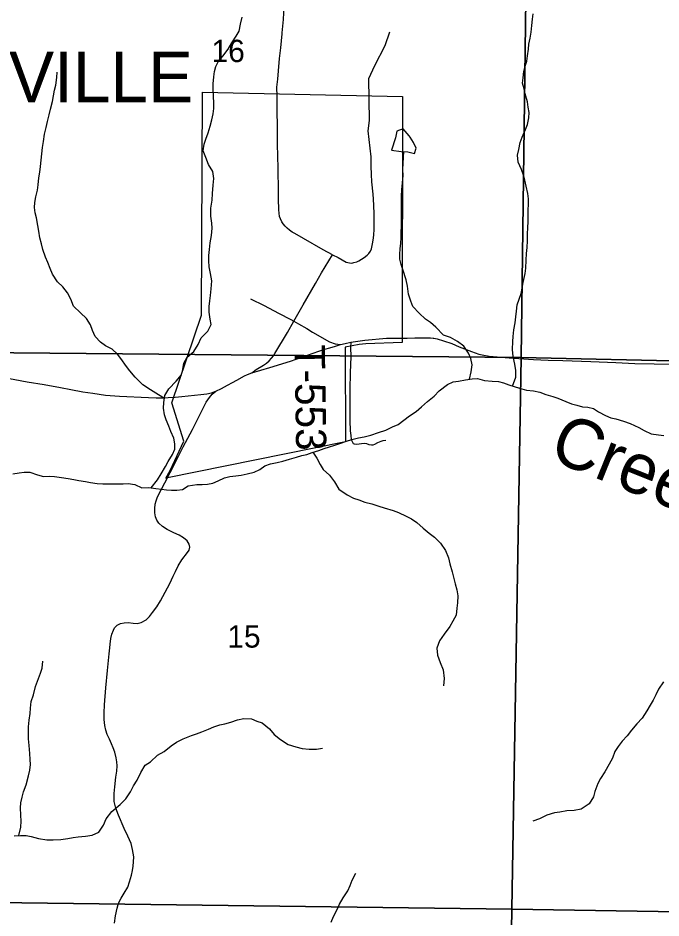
# Model space of a CAD drawing. Extents: x 0 to 191, y 0 to 55.
# Drawn here: x 187.422 to 188.627, y 50.382 to 52.068 of the extents above; entities that cross this region are included whole.
import ezdxf

# ---------------------------------------------------------------- set-up
doc = ezdxf.new("R2010")
doc.units = 0
for name, color, linetype in [('GM_X_City_Street', 7, 'Continuous'), ('GM_X_Corporation', 7, 'Continuous'), ('GM_X_Corporation_Text', 7, 'Continuous'), ('GM_X_Minor_Lake', 7, 'Continuous'), ('GM_X_Minor_River', 7, 'Continuous'), ('GM_X_Minor_River_Text', 7, 'Continuous'), ('GM_X_Section_Text', 7, 'Continuous'), ('GM_X_State_Route', 7, 'Continuous'), ('GM_X_Township_Road', 7, 'Continuous'), ('GM_X_Township_Road_Text', 7, 'Continuous')]:
    doc.layers.add(name, color=color, linetype=linetype)

msp = doc.modelspace()

# ---------------------------------------------------------------- linework, layer by layer
at = {"layer": 'GM_X_City_Street'}
for points in [[(187.8578, 51.5417), (187.8832, 51.5291), (187.9106, 51.5152), (187.9332, 51.5032), (187.9392, 51.4997), (187.9478, 51.4948)], [(187.9478, 51.4948), (187.9633, 51.486), (187.9742, 51.4791), (188.0061, 51.461), (188.0168, 51.4577), (188.0267, 51.4565)]]:
    msp.add_lwpolyline(points, dxfattribs=at)
at = {"layer": 'GM_X_Corporation'}
for points in [[(187.3608, 52.4557), (188.3785, 52.4395), (188.3652, 51.4321), (187.3457, 51.441)], [(188.3785, 52.4395), (189.3902, 52.4217), (189.3789, 51.4094), (188.3652, 51.4321)], [(187.6988, 51.2057), (187.7072, 51.2202), (187.7328, 51.2751), (187.7105, 51.3468), (187.7659, 51.5111), (187.7676, 51.929), (188.1426, 51.9211), (188.1418, 51.4599), (188.074, 51.4574), (188.0613, 51.4561), (188.0352, 51.4511), (188.036, 51.2741)], [(188.3652, 51.4321), (188.3474, 50.3984), (187.3319, 50.4112), (187.3457, 51.441)], [(189.3789, 51.4094), (189.3658, 50.3822), (188.3474, 50.3984), (188.3652, 51.4321)], [(187.3319, 50.4112), (188.3474, 50.3984), (188.3312, 49.3807), (187.315, 49.3912)], [(188.3474, 50.3984), (189.3658, 50.3822), (189.3602, 49.3699), (188.3312, 49.3807)]]:
    msp.add_lwpolyline(points, close=True, dxfattribs=at)
at = {"layer": 'GM_X_Minor_Lake'}
for points in [[(188.1568, 51.8446), (188.1552, 51.8471), (188.1438, 51.86), (188.1324, 51.8557), (188.1298, 51.8436), (188.122, 51.8205)], [(188.122, 51.8205), (188.1404, 51.8178), (188.153, 51.8171), (188.1655, 51.8141), (188.1681, 51.8243), (188.1632, 51.8346), (188.1568, 51.8446)]]:
    msp.add_lwpolyline(points, dxfattribs=at)
at = {"layer": 'GM_X_Minor_River'}
for points in [[(187.6719, 51.1877), (187.6834, 51.2024), (187.6902, 51.2142), (187.6982, 51.2275), (187.7035, 51.2371), (187.7118, 51.25), (187.7159, 51.2603), (187.7159, 51.2701), (187.714, 51.2804), (187.7083, 51.2929), (187.7045, 51.3031), (187.6999, 51.3149), (187.6968, 51.3247), (187.6949, 51.3369), (187.6953, 51.3475), (187.6971, 51.3608), (187.7047, 51.373), (187.7187, 51.3874), (187.7282, 51.3992), (187.7308, 51.4091), (187.733, 51.4213), (187.7391, 51.4327), (187.7516, 51.4433), (187.7599, 51.4559), (187.7656, 51.4688), (187.7781, 51.481), (187.7841, 51.4936), (187.7822, 51.5034), (187.7806, 51.5167), (187.7806, 51.5273), (187.7813, 51.538), (187.7828, 51.5479), (187.7839, 51.5604), (187.7851, 51.5752), (187.7827, 51.5892), (187.7801, 51.6014), (187.7797, 51.6131), (187.78, 51.623), (187.7807, 51.634), (187.7822, 51.6466), (187.7849, 51.6606), (187.786, 51.6743), (187.7852, 51.6838), (187.7836, 51.6967), (187.7836, 51.7119), (187.7858, 51.7263), (187.7866, 51.7388), (187.7881, 51.7544), (187.7892, 51.7673), (187.7869, 51.7802), (187.7792, 51.7935), (187.7743, 51.8064), (187.7689, 51.8193), (187.7708, 51.8314), (187.7742, 51.8409), (187.7787, 51.8527), (187.7825, 51.8653), (187.7855, 51.877), (187.7877, 51.8881), (187.7889, 51.8983), (187.7888, 51.909), (187.7884, 51.9211), (187.7876, 51.934), (187.7876, 51.9443), (187.7891, 51.9579), (187.7902, 51.9674), (187.7928, 51.9769), (187.7981, 51.9868), (187.8057, 51.9963), (187.8159, 52.0093), (187.8227, 52.0211), (187.831, 52.0336), (187.8363, 52.0432), (187.8393, 52.0561), (187.8423, 52.0694)], [(188.3489, 51.3783), (188.3554, 51.3948), (188.355, 51.4077), (188.3531, 51.4191), (188.35, 51.4335), (188.3489, 51.4471), (188.3496, 51.4616), (188.3503, 51.4711), (188.3514, 51.4836), (188.3537, 51.4965), (188.3552, 51.5079), (188.3563, 51.5189), (188.3578, 51.5303), (188.3615, 51.5409), (188.3649, 51.5516), (188.3672, 51.5615), (188.3691, 51.5725), (188.3728, 51.5892), (188.3739, 51.5995), (188.3747, 51.6139), (188.3754, 51.6268), (188.3765, 51.6378), (188.3769, 51.6507), (188.3772, 51.6629), (188.3776, 51.6754), (188.3783, 51.686), (188.3782, 51.7088), (188.3786, 51.7187), (188.3786, 51.7293), (188.3778, 51.7388), (188.3747, 51.7528), (188.3717, 51.7642), (188.3694, 51.7737), (188.3659, 51.7843), (188.3598, 51.798), (188.3583, 51.8109), (188.3605, 51.8215), (188.3635, 51.8348), (188.3673, 51.8447), (188.3733, 51.8588), (188.3767, 51.8683), (188.3797, 51.8808), (188.3801, 51.8907), (188.3785, 51.9009), (188.377, 51.9108), (188.3728, 51.9256), (188.3705, 51.9351), (188.3678, 51.9457), (188.3686, 51.9556), (188.3704, 51.9677), (188.3727, 51.9776), (188.3757, 51.9871), (188.3772, 51.997), (188.3791, 52.0095), (188.3798, 52.019), (188.382, 52.0301), (188.3839, 52.0415), (188.3854, 52.0536), (188.3865, 52.0654), (188.3876, 52.0756)], [(187.6963, 51.3552), (187.6854, 51.3619), (187.6705, 51.3713), (187.6561, 51.3808), (187.6416, 51.3948), (187.6314, 51.4069), (187.6234, 51.4175), (187.6165, 51.4274), (187.6085, 51.4383), (187.5983, 51.4474), (187.5861, 51.4538), (187.5766, 51.4606), (187.5667, 51.4712), (187.5614, 51.4826), (187.5579, 51.4932), (187.5507, 51.505), (187.5393, 51.5156), (187.526, 51.5277), (187.521, 51.5413), (187.5145, 51.5531), (187.5062, 51.5644), (187.4963, 51.5739), (187.4864, 51.5879), (187.4822, 51.5985), (187.478, 51.6099), (187.4734, 51.6201), (187.4684, 51.6342), (187.4658, 51.6448), (187.4631, 51.6562), (187.4611, 51.6683), (187.4592, 51.6793), (187.4565, 51.6934), (187.4542, 51.7029), (187.4531, 51.7127), (187.4534, 51.7222), (187.4557, 51.7329), (187.4583, 51.7454), (187.4598, 51.7556), (187.4613, 51.7686), (187.4632, 51.7792), (187.4639, 51.7895), (187.4654, 51.8016), (187.468, 51.8255), (187.4695, 51.8366), (187.4717, 51.8502), (187.4747, 51.8628), (187.4774, 51.8738), (187.4804, 51.8863), (187.483, 51.8974), (187.4864, 51.9114), (187.4886, 51.9221), (187.4905, 51.9327), (187.4931, 51.9422), (187.495, 51.9566), (187.4954, 51.9661)], [(188.2684, 51.3911), (188.2712, 51.4048), (188.273, 51.4184), (188.2707, 51.4302), (188.2665, 51.44), (188.2574, 51.4533), (188.2456, 51.462), (188.2327, 51.4692), (188.2198, 51.4737), (188.2053, 51.4888), (188.1954, 51.4971), (188.1859, 51.5036), (188.1738, 51.5149), (188.162, 51.5274), (188.1582, 51.5373), (188.154, 51.5502), (188.152, 51.5653), (188.1493, 51.5771), (188.1432, 51.5968), (188.1402, 51.6063), (188.1375, 51.6158), (188.1375, 51.6257), (188.1386, 51.6352), (188.1393, 51.6458), (188.1401, 51.656), (188.1404, 51.6663), (188.1408, 51.6788), (188.1407, 51.6887), (188.1411, 51.7012), (188.141, 51.7335), (188.1417, 51.7464), (188.1429, 51.7593), (188.144, 51.773), (188.1436, 51.784), (188.1453, 51.8175)], [(188.1685, 51.3308), (188.1783, 51.3392), (188.1897, 51.3491), (188.2018, 51.3597), (188.2117, 51.3696), (188.2268, 51.3811), (188.2378, 51.386), (188.2477, 51.3876), (188.2606, 51.3899), (188.2731, 51.3919), (188.2833, 51.3923), (188.2966, 51.3889), (188.3107, 51.3878), (188.3228, 51.3867), (188.3323, 51.3841), (188.3418, 51.3807), (188.352, 51.3773), (188.3619, 51.3743), (188.3752, 51.3705), (188.3885, 51.3691), (188.3999, 51.3668), (188.4113, 51.3627), (188.4242, 51.3589), (188.4341, 51.3555), (188.4489, 51.3495), (188.4595, 51.345), (188.4694, 51.3424), (188.4804, 51.3397), (188.4899, 51.3386), (188.5005, 51.336), (188.51, 51.3303), (188.5233, 51.3232), (188.5332, 51.319), (188.5427, 51.3168), (188.5571, 51.3123), (188.5693, 51.3081), (188.5856, 51.301), (188.5955, 51.2949), (188.6088, 51.2889), (188.6224, 51.2867), (188.6323, 51.2856)], [(187.4121, 51.2141), (187.4242, 51.216), (187.4337, 51.2172), (187.4443, 51.2172), (187.4588, 51.212), (187.4698, 51.209), (187.4804, 51.2098), (187.4903, 51.209), (187.5036, 51.2072), (187.5161, 51.2049), (187.5267, 51.2031), (187.5362, 51.2016), (187.5487, 51.1994), (187.5582, 51.1979), (187.5704, 51.196), (187.581, 51.1953), (187.5909, 51.1949), (187.606, 51.195), (187.619, 51.195), (187.6284, 51.1958), (187.6413, 51.1936), (187.6539, 51.1879), (187.6672, 51.1883), (187.6804, 51.1865), (187.6907, 51.1854), (187.7002, 51.1839), (187.7097, 51.1832), (187.7195, 51.1832), (187.7302, 51.1848), (187.7411, 51.1916), (187.7571, 51.1939), (187.7669, 51.194), (187.7772, 51.1948), (187.7871, 51.1967), (187.7973, 51.2005), (187.809, 51.2063), (187.8189, 51.2086), (187.8303, 51.2101), (187.8401, 51.2117), (187.8515, 51.2136), (187.8644, 51.2171), (187.875, 51.2217), (187.8849, 51.2289), (187.8955, 51.2327), (187.908, 51.2354), (187.9183, 51.2377), (187.9311, 51.2412), (187.944, 51.245), (187.9539, 51.2481), (187.9634, 51.2504), (187.9736, 51.2539), (187.9858, 51.2577), (187.9956, 51.2611), (188.0059, 51.2642), (188.0157, 51.2677), (188.0252, 51.2707), (188.0377, 51.2753), (188.0476, 51.2784), (188.0601, 51.2811), (188.0711, 51.2834), (188.0836, 51.2865), (188.098, 51.2911), (188.1113, 51.2957), (188.1238, 51.3018), (188.1344, 51.3064), (188.1454, 51.3144), (188.156, 51.3224), (188.1685, 51.3308)], [(187.9747, 51.2542), (187.982, 51.2433), (187.9881, 51.2315), (187.9938, 51.2217), (188.0056, 51.2114), (188.0151, 51.1986), (188.0235, 51.1849), (188.0387, 51.1743), (188.0508, 51.1683), (188.0607, 51.1649), (188.0721, 51.1608), (188.0854, 51.1574), (188.0983, 51.1533), (188.1086, 51.1503), (188.1253, 51.1454), (188.1351, 51.1412), (188.1496, 51.1348), (188.1598, 51.1296), (188.1697, 51.1224), (188.1815, 51.1118), (188.1929, 51.1027), (188.2024, 51.0955), (188.2138, 51.0838), (188.2233, 51.0702), (188.2291, 51.0565), (188.2314, 51.0451), (188.236, 51.03), (188.2386, 51.0205), (188.2417, 51.0076), (188.2444, 50.9966), (188.2463, 50.9852), (188.2459, 50.9719), (188.2448, 50.962), (188.2433, 50.9491), (188.2373, 50.9381), (188.2312, 50.9278), (188.2206, 50.9138), (188.2123, 50.9008), (188.207, 50.8871), (188.2086, 50.8742), (188.2136, 50.8606), (188.2189, 50.8466), (188.2208, 50.8302), (188.2193, 50.817)], [(187.4233, 50.536), (187.4276, 50.5521), (187.428, 50.5631), (187.4276, 50.5741), (187.4268, 50.5882), (187.4275, 50.5977), (187.4298, 50.6083), (187.4324, 50.6182), (187.4373, 50.6311), (187.4418, 50.6482), (187.4445, 50.6588), (187.4456, 50.6691), (187.4448, 50.679), (187.444, 50.69), (187.4428, 50.7051), (187.442, 50.7177), (187.442, 50.7397), (187.4427, 50.7526), (187.4446, 50.7647), (187.4457, 50.7746), (187.4468, 50.7875), (187.451, 50.7997), (187.4547, 50.8156), (187.4645, 50.8403), (187.4672, 50.8498), (187.4687, 50.8631)], [(188.6318, 50.824), (188.6227, 50.8106), (188.6174, 50.7996), (188.6125, 50.7901), (188.6069, 50.7802), (188.6008, 50.7696), (188.5917, 50.7559), (188.5819, 50.7456), (188.5717, 50.7338), (188.5637, 50.7231), (188.5546, 50.7133), (188.5467, 50.703), (188.541, 50.6935), (188.5361, 50.6813), (188.5301, 50.6699), (188.5221, 50.6555), (188.5138, 50.6433), (188.5089, 50.6338), (188.5032, 50.6189), (188.5006, 50.6087), (188.4927, 50.5958), (188.4779, 50.5855), (188.4646, 50.5831), (188.4506, 50.5823), (188.4373, 50.58), (188.4274, 50.5785), (188.4134, 50.5743), (188.3998, 50.5678), (188.3872, 50.5632)], [(187.7316, 50.7175), (187.7471, 50.7236), (187.7566, 50.727), (187.7665, 50.7305), (187.779, 50.7358), (187.7888, 50.74), (187.8002, 50.7439), (187.8097, 50.7458), (187.8211, 50.7489), (187.8336, 50.7527), (187.8453, 50.7554), (187.8594, 50.7547), (187.8696, 50.7505), (187.8795, 50.7472), (187.8932, 50.7362), (187.9019, 50.7256), (187.9141, 50.7161), (187.9282, 50.7071), (187.9426, 50.7022), (187.9547, 50.6996), (187.9676, 50.6981), (187.9813, 50.6981), (187.9927, 50.7001)], [(187.4151, 50.5358), (187.4269, 50.5362), (187.4371, 50.5362), (187.4466, 50.5347), (187.4607, 50.531), (187.4759, 50.5284), (187.488, 50.528), (187.5024, 50.5288), (187.5153, 50.5304), (187.5252, 50.5327), (187.535, 50.5335), (187.5483, 50.535), (187.5612, 50.537), (187.5734, 50.5423), (187.5824, 50.5557), (187.587, 50.5674), (187.5979, 50.5811), (187.6138, 50.5945), (187.6241, 50.6048), (187.6331, 50.6181), (187.6384, 50.6291), (187.6452, 50.6401), (187.6524, 50.6542), (187.6604, 50.6679), (187.6702, 50.6744), (187.6835, 50.6869), (187.696, 50.6938), (187.7092, 50.7041), (187.7191, 50.711), (187.7316, 50.7175)], [(188.009, 50.3741), (188.0135, 50.3843), (188.0199, 50.3965), (188.0248, 50.4075), (188.0316, 50.4197), (188.04, 50.4326), (188.0449, 50.4425), (188.0486, 50.4528), (188.0554, 50.4657)]]:
    msp.add_lwpolyline(points, dxfattribs=at)
at = {"layer": 'GM_X_State_Route'}
for points in [[(187.9169, 52.0383), (187.917, 52.0403), (187.9194, 52.0648), (187.9206, 52.0901)], [(187.9074, 51.9386), (187.9088, 51.9532), (187.9106, 51.9688), (187.9122, 51.9918), (187.9148, 52.0119), (187.9169, 52.0383)], [(187.8604, 51.4034), (187.8686, 51.4092), (187.8822, 51.4175), (187.8879, 51.4213), (187.893, 51.4259), (187.8972, 51.4304), (187.9008, 51.4352), (187.9035, 51.4391), (187.9269, 51.4788), (187.9392, 51.4997), (187.9566, 51.5308), (187.9797, 51.5706), (187.9908, 51.5902), (188.0117, 51.6242), (187.994, 51.6337), (187.9573, 51.6546), (187.9408, 51.664), (187.9358, 51.6668), (187.9311, 51.6702), (187.9266, 51.6739), (187.9225, 51.678), (187.9189, 51.6822), (187.9163, 51.6862), (187.914, 51.6915), (187.9124, 51.6963), (187.9109, 51.7088), (187.9104, 51.7289), (187.9105, 51.7436), (187.9097, 51.7857), (187.9092, 51.8097), (187.9086, 51.831), (187.9084, 51.8391), (187.9084, 51.8652), (187.9081, 51.8931), (187.9076, 51.9217), (187.9074, 51.9386)], [(187.8604, 51.4034), (187.8938, 51.413), (187.9326, 51.4249), (187.9861, 51.4438), (187.9973, 51.4473), (188.0067, 51.4502), (188.0169, 51.4532), (188.0267, 51.4565), (188.035, 51.4583), (188.0456, 51.4607), (188.0724, 51.4643), (188.113, 51.4679), (188.1468, 51.4681), (188.1516, 51.4683)], [(188.1516, 51.4683), (188.1661, 51.4686), (188.1808, 51.4687), (188.1955, 51.4684), (188.1999, 51.4679)], [(188.1999, 51.4679), (188.2016, 51.4678), (188.2078, 51.4667), (188.2196, 51.4633), (188.2349, 51.4578), (188.2488, 51.452), (188.2719, 51.4428), (188.286, 51.4378), (188.2951, 51.4359), (188.3053, 51.4345), (188.3428, 51.4312), (188.3884, 51.4281), (188.4157, 51.4266), (188.443, 51.4262), (188.4955, 51.4246), (188.5428, 51.4222), (188.5782, 51.4206), (188.6147, 51.4201), (188.6519, 51.4193)], [(187.3928, 51.3953), (187.4392, 51.3861), (187.4709, 51.3814), (187.5017, 51.3756), (187.5208, 51.3717), (187.5433, 51.3678), (187.5622, 51.3652), (187.5858, 51.3615), (187.6124, 51.3596), (187.6665, 51.3571), (187.681, 51.3563), (187.6957, 51.3565), (187.7036, 51.3569), (187.7164, 51.3578)], [(187.7931, 51.3686), (187.8032, 51.374), (187.8145, 51.3799), (187.8241, 51.3851), (187.832, 51.3894), (187.8463, 51.3972), (187.8524, 51.4003), (187.8604, 51.4034)], [(187.7164, 51.3578), (187.7292, 51.3587), (187.7647, 51.3625)], [(187.7285, 51.2585), (187.7316, 51.2647), (187.7489, 51.2967), (187.7674, 51.333), (187.7749, 51.3482), (187.7807, 51.3571), (187.7861, 51.3629), (187.7931, 51.3686)], [(187.7647, 51.3625), (187.7758, 51.3638), (187.7845, 51.3654), (187.7931, 51.3686)], [(187.697, 51.1968), (187.7071, 51.2165), (187.7228, 51.2469), (187.7285, 51.2585)], [(187.6029, 50.3721), (187.605, 50.3855), (187.6079, 50.3999), (187.6099, 50.4069), (187.612, 50.4134), (187.6151, 50.4192), (187.6213, 50.4282), (187.6277, 50.4398), (187.631, 50.4493), (187.6347, 50.4621), (187.6365, 50.4709), (187.6379, 50.4786), (187.6388, 50.4871), (187.639, 50.4964), (187.6367, 50.51), (187.634, 50.5211), (187.6277, 50.535), (187.6213, 50.5493), (187.6102, 50.5747), (187.6052, 50.5876), (187.6025, 50.5999), (187.602, 50.6069), (187.602, 50.6153), (187.6034, 50.6276), (187.6056, 50.6453), (187.6072, 50.6569), (187.6076, 50.6671), (187.6074, 50.6742), (187.6063, 50.6821), (187.6038, 50.6924), (187.6004, 50.7008), (187.597, 50.7083), (187.5933, 50.7167), (187.5893, 50.7255), (187.5868, 50.7337), (187.5847, 50.7427), (187.5834, 50.7534), (187.5833, 50.7661), (187.5843, 50.7814), (187.5866, 50.8132), (187.5895, 50.8452), (187.5929, 50.8768), (187.594, 50.8881), (187.5945, 50.8947), (187.5959, 50.9056), (187.5977, 50.9133), (187.6009, 50.9213), (187.6032, 50.9255), (187.6076, 50.9301), (187.6142, 50.9333), (187.6211, 50.9349), (187.6288, 50.9356), (187.6379, 50.9344), (187.6453, 50.9338), (187.6529, 50.9354), (187.6622, 50.9406), (187.6683, 50.9467), (187.6744, 50.9542), (187.6821, 50.9647), (187.6894, 50.9762), (187.698, 50.9924), (187.7065, 51.0085), (187.7131, 51.0219), (187.7171, 51.031), (187.7221, 51.0416), (187.7294, 51.0527), (187.7399, 51.0664), (187.7428, 51.0707), (187.7442, 51.0766), (187.7428, 51.082), (187.7391, 51.0884), (187.7324, 51.0939), (187.724, 51.0988), (187.7139, 51.1034), (187.7015, 51.1093), (187.6926, 51.1152), (187.6863, 51.1213), (187.6821, 51.127), (187.6799, 51.1334), (187.6787, 51.1407), (187.6785, 51.149), (187.6792, 51.1568), (187.681, 51.1631), (187.6837, 51.1709), (187.691, 51.1852), (187.697, 51.1968)]]:
    msp.add_lwpolyline(points, dxfattribs=at)
at = {"layer": 'GM_X_Township_Road'}
for points in [[(188.0117, 51.6242), (188.0219, 51.6191), (188.0374, 51.6102), (188.0432, 51.6089), (188.0476, 51.6086), (188.0516, 51.6096), (188.0569, 51.6112), (188.061, 51.6132), (188.0656, 51.6159), (188.0708, 51.6194), (188.0763, 51.6235), (188.0795, 51.6266), (188.0827, 51.6313), (188.0844, 51.6352), (188.0852, 51.6386), (188.0867, 51.6446), (188.088, 51.6517), (188.0892, 51.6608), (188.0896, 51.6721), (188.0893, 51.688), (188.0893, 51.7012), (188.0888, 51.7163), (188.0881, 51.7286), (188.0876, 51.7376), (188.0855, 51.7608), (188.0844, 51.7749), (188.0842, 51.79), (188.0837, 51.8078), (188.0782, 51.8562), (188.0806, 51.8759), (188.0794, 51.9544), (188.0908, 51.9787), (188.11, 52.0162), (188.119, 52.042)], [(188.0456, 51.4607), (188.0454, 51.4507), (188.0457, 51.4337), (188.0446, 51.4028), (188.0439, 51.3716), (188.0439, 51.3431), (188.0443, 51.3139), (188.0448, 51.2943), (188.0457, 51.2858), (188.0468, 51.2782), (188.0482, 51.2744), (188.0503, 51.2709), (188.0522, 51.27), (188.0559, 51.2696), (188.0615, 51.27), (188.0659, 51.2706), (188.0713, 51.2711), (188.0752, 51.2705), (188.0797, 51.2691), (188.0844, 51.2683), (188.0876, 51.2683), (188.0906, 51.2692), (188.0967, 51.2724), (188.1025, 51.2754), (188.1065, 51.2763), (188.1117, 51.2771)]]:
    msp.add_lwpolyline(points, dxfattribs=at)

# ---------------------------------------------------------------- texts
at = {"layer": 'GM_X_Corporation_Text'}
msp.add_text('BATESVILLE', height=0.0947, rotation=0, dxfattribs=at).set_placement((186.99, 51.9099))
at = {"layer": 'GM_X_Minor_River_Text'}
msp.add_text('Creek', height=0.0947, rotation=338.1293, dxfattribs=at).set_placement((188.4138, 51.2425))
at = {"layer": 'GM_X_Section_Text'}
for s, p in [('16', (187.7849, 51.9853)), ('15', (187.8144, 50.8883))]:
    msp.add_text(s, height=0.04186, rotation=0, dxfattribs=at).set_placement(p)
at = {"layer": 'GM_X_Township_Road_Text'}
msp.add_text('T-553', height=0.05682, rotation=270.8421, dxfattribs=at).set_placement((187.9404, 51.4555))

doc.saveas('drawing.dxf')
